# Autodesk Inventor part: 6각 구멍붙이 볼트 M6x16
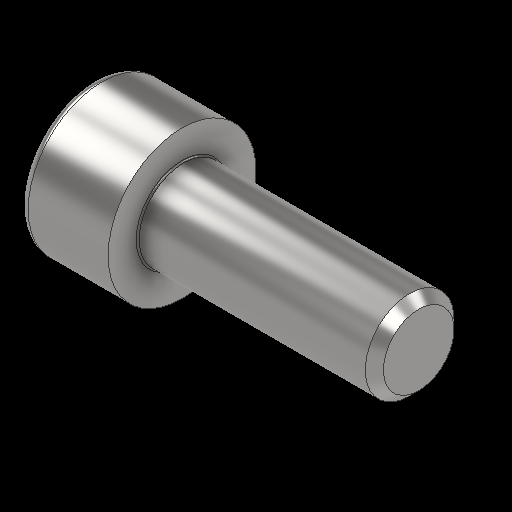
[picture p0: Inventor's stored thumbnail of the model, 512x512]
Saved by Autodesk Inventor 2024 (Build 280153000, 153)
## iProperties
Created: 2025-10
Part Number: 6각 구멍붙이 볼트 M6x16
Material: 강철, 연강
Description: 6각머리 태핑 나사
Document SubType Name: Modeling
Designer: EDU03
Density: 7.85 g/cm^3
Appearance: 기본값
Author: jhkim
Sending System: Autodesk Inventor 2026
Preprocessor: ST-DEVELOPER v20.1
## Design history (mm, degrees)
node "6각 구멍붙이 볼트 M6x161"
node "솔리드1"
body "Solid1"
